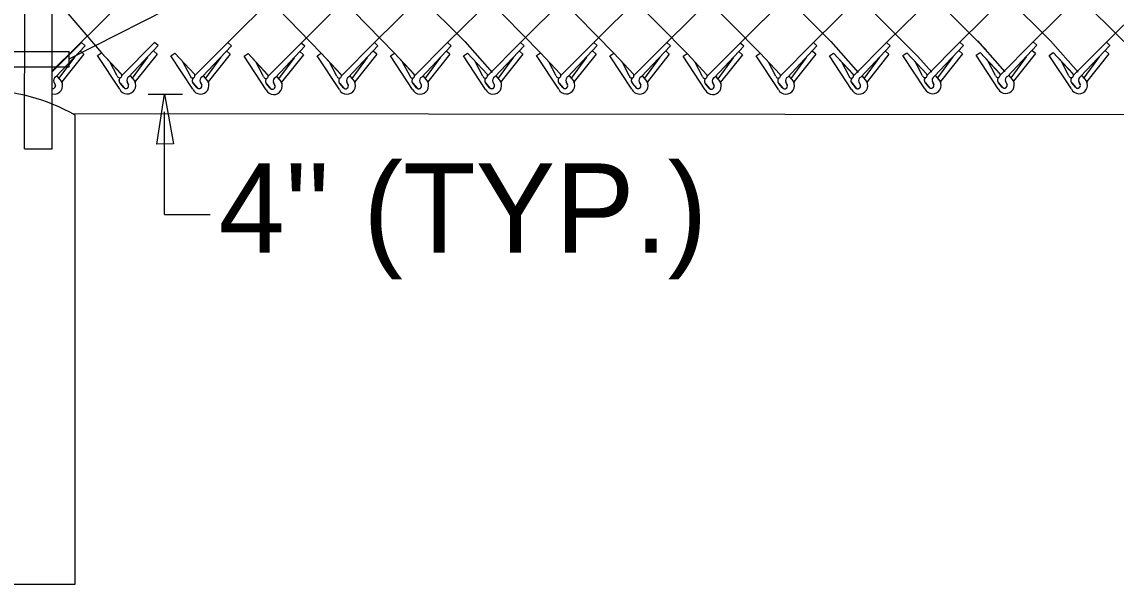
# Model space of a CAD drawing. Extents: x 0 to 1270, y 0 to 830.
# Drawn here: x 53.5 to 113.7, y 352.2 to 383.2 of the extents above; entities that cross this region are included whole.
import ezdxf

# ---------------------------------------------------------------- set-up
doc = ezdxf.new("R2010")
doc.units = 0
for name, color, linetype in [('CT_Dimensions', 7, 'Continuous'), ('sb_Chainlink Fence', 7, 'Continuous'), ('sb_Existing Concrete', 7, 'Continuous'), ('sb_Existing Structural Steel', 7, 'Continuous')]:
    doc.layers.add(name, color=color, linetype=linetype)

msp = doc.modelspace()

# ---------------------------------------------------------------- linework, layer by layer
at = {"layer": 'CT_Dimensions'}
for p, q in [((60.451, 379.198), (62.33, 379.198)), ((61.341, 372.57), (61.341, 378.225)), ((61.341, 372.57), (63.855, 372.57))]:
    msp.add_line(p, q, dxfattribs=at)
msp.add_lwpolyline([(60.924, 376.439), (61.34, 379.193), (61.84, 376.453)], close=True, dxfattribs=at)
at = {"layer": 'sb_Chainlink Fence'}
for p, q in [((60.791, 435.304), (114.124, 382.089)), ((68.863, 382.004), (122.519, 435.835)), ((101.072, 382.029), (154.956, 435.546)), ((64.832, 382.034), (118.139, 435.235)), ((72.891, 382.026), (126.395, 435.183)), ((76.918, 382.029), (130.422, 435.192)), ((80.932, 382.032), (134.453, 435.222)), ((84.959, 382.042), (138.481, 435.199)), ((88.986, 382.034), (142.508, 435.196)), ((93.017, 382.004), (146.522, 435.194)), ((105.111, 382.053), (158.608, 435.222)), ((109.138, 382.063), (162.636, 435.199)), ((113.165, 382.055), (166.662, 435.196)), ((57.834, 434.248), (110.093, 382.118)), ((55.231, 432.935), (106.547, 381.637)), ((97.046, 382.026), (147.698, 432.692)), ((55.226, 428.91), (102.798, 381.262)), ((55.221, 424.884), (98, 382.093)), ((55.216, 420.858), (94.125, 381.448)), ((55.211, 416.833), (90.096, 381.426)), ((55.207, 412.807), (86.065, 381.456)), ((55.202, 408.781), (82.038, 381.464)), ((55.197, 404.755), (77.86, 382.095)), ((55.192, 400.73), (73.996, 381.451)), ((55.187, 396.704), (69.97, 381.448)), ((55.168, 380.467), (59.118, 384.405)), ((55.173, 384.627), (57.883, 381.464)), ((55.164, 380.412), (56.778, 382.032)), ((55.363, 380.139), (56.976, 381.852)), ((56.976, 381.852), (56.778, 382.032)), ((58.991, 380.221), (60.804, 382.042)), ((59.39, 380.149), (61.002, 381.863)), ((61.002, 381.863), (60.804, 382.042)), ((63.018, 380.212), (64.832, 382.034)), ((63.417, 380.141), (65.029, 381.854)), ((65.029, 381.854), (64.832, 382.034)), ((67.049, 380.183), (68.863, 382.004)), ((67.448, 380.111), (69.061, 381.825)), ((69.061, 381.825), (68.863, 382.004)), ((71.077, 380.205), (72.891, 382.026)), ((71.476, 380.134), (73.089, 381.847)), ((73.089, 381.847), (72.891, 382.026)), ((75.104, 380.208), (76.918, 382.029)), ((75.503, 380.136), (77.115, 381.85)), ((77.115, 381.85), (76.918, 382.029)), ((77.86, 382.095), (79.378, 380.386)), ((79.118, 380.21), (80.932, 382.032)), ((79.517, 380.139), (81.13, 381.852)), ((81.13, 381.852), (80.932, 382.032)), ((83.145, 380.221), (84.959, 382.042)), ((83.544, 380.149), (85.157, 381.863)), ((85.157, 381.863), (84.959, 382.042)), ((87.172, 380.212), (88.986, 382.034)), ((87.571, 380.141), (89.184, 381.854)), ((89.184, 381.854), (88.986, 382.034)), ((91.204, 380.183), (93.017, 382.004)), ((91.602, 380.111), (93.215, 381.825)), ((93.215, 381.825), (93.017, 382.004)), ((95.232, 380.205), (97.046, 382.026)), ((95.631, 380.134), (97.243, 381.847)), ((97.243, 381.847), (97.046, 382.026)), ((98, 382.093), (99.518, 380.384)), ((99.258, 380.208), (101.072, 382.029)), ((99.657, 380.136), (101.27, 381.85)), ((101.27, 381.85), (101.072, 382.029)), ((103.297, 380.232), (105.111, 382.053)), ((103.696, 380.16), (105.309, 381.874)), ((105.309, 381.874), (105.111, 382.053)), ((106.066, 382.127), (107.583, 380.418)), ((107.324, 380.242), (109.138, 382.063)), ((107.723, 380.171), (109.336, 381.884)), ((109.336, 381.884), (109.138, 382.063)), ((110.093, 382.118), (111.611, 380.41)), ((111.351, 380.233), (113.165, 382.055)), ((111.75, 380.162), (113.363, 381.876)), ((113.363, 381.876), (113.165, 382.055)), ((56.389, 381.223), (55.54, 380.068)), ((56.908, 381.389), (55.702, 379.872)), ((56.908, 381.389), (56.71, 381.569)), ((57.66, 381.312), (57.883, 381.464)), ((58.879, 379.467), (57.66, 381.312)), ((57.883, 381.464), (58.961, 380.302)), ((57.883, 381.464), (58.968, 380.295)), ((60.416, 381.234), (59.567, 380.079)), ((60.935, 381.4), (59.729, 379.882)), ((60.935, 381.4), (60.737, 381.579)), ((61.688, 381.303), (61.91, 381.456)), ((62.906, 379.459), (61.688, 381.303)), ((61.91, 381.456), (62.988, 380.294)), ((61.91, 381.456), (62.995, 380.287)), ((64.443, 381.225), (63.594, 380.07)), ((64.962, 381.391), (63.756, 379.874)), ((64.962, 381.391), (64.764, 381.571)), ((65.719, 381.274), (65.942, 381.426)), ((66.937, 379.429), (65.719, 381.274)), ((65.942, 381.426), (67.02, 380.264)), ((65.942, 381.426), (67.027, 380.257)), ((68.474, 381.196), (67.625, 380.041)), ((68.993, 381.362), (67.787, 379.844)), ((68.993, 381.362), (68.796, 381.541)), ((69.747, 381.296), (69.97, 381.448)), ((70.965, 379.452), (69.747, 381.296)), ((69.97, 381.448), (71.048, 380.287)), ((69.97, 381.448), (71.055, 380.28)), ((72.502, 381.218), (71.654, 380.063)), ((73.022, 381.384), (71.815, 379.867)), ((73.022, 381.384), (72.824, 381.563)), ((73.774, 381.299), (73.996, 381.451)), ((74.992, 379.454), (73.774, 381.299)), ((73.996, 381.451), (75.074, 380.289)), ((73.996, 381.451), (75.081, 380.282)), ((76.529, 381.221), (75.68, 380.066)), ((77.048, 381.387), (75.842, 379.869)), ((77.048, 381.387), (76.85, 381.566)), ((77.788, 381.301), (78.011, 381.454)), ((79.006, 379.457), (77.788, 381.301)), ((78.011, 381.454), (79.089, 380.292)), ((78.011, 381.454), (79.096, 380.285)), ((80.543, 381.223), (79.695, 380.068)), ((81.063, 381.389), (79.856, 379.872)), ((81.063, 381.389), (80.865, 381.569)), ((81.815, 381.312), (82.038, 381.464)), ((83.033, 379.467), (81.815, 381.312)), ((82.038, 381.464), (83.116, 380.302)), ((82.038, 381.464), (83.123, 380.295)), ((84.57, 381.234), (83.722, 380.079)), ((85.09, 381.4), (83.883, 379.882)), ((85.09, 381.4), (84.892, 381.579)), ((85.842, 381.303), (86.065, 381.456)), ((87.06, 379.459), (85.842, 381.303)), ((86.065, 381.456), (87.143, 380.294)), ((86.065, 381.456), (87.15, 380.287)), ((88.597, 381.225), (87.749, 380.07)), ((89.117, 381.391), (87.91, 379.874)), ((89.117, 381.391), (88.919, 381.571)), ((89.873, 381.274), (90.096, 381.426)), ((91.091, 379.429), (89.873, 381.274)), ((90.096, 381.426), (91.174, 380.264)), ((90.096, 381.426), (91.181, 380.257)), ((92.628, 381.196), (91.78, 380.041)), ((93.148, 381.362), (91.942, 379.844)), ((93.148, 381.362), (92.95, 381.541)), ((93.902, 381.296), (94.125, 381.448)), ((95.12, 379.452), (93.902, 381.296)), ((94.125, 381.448), (95.203, 380.287)), ((94.125, 381.448), (95.209, 380.28)), ((96.657, 381.218), (95.808, 380.063)), ((97.176, 381.384), (95.97, 379.867)), ((97.176, 381.384), (96.978, 381.563)), ((97.928, 381.299), (98.151, 381.451)), ((99.146, 379.454), (97.928, 381.299)), ((98.151, 381.451), (99.229, 380.289)), ((98.151, 381.451), (99.236, 380.282)), ((100.683, 381.221), (99.835, 380.066)), ((101.203, 381.387), (99.996, 379.869)), ((101.203, 381.387), (101.005, 381.566)), ((101.967, 381.323), (102.19, 381.475)), ((103.185, 379.478), (101.967, 381.323)), ((102.19, 381.475), (103.268, 380.313)), ((102.19, 381.475), (103.275, 380.306)), ((102.798, 381.262), (103.557, 380.408)), ((104.722, 381.245), (103.874, 380.09)), ((105.242, 381.411), (104.035, 379.893)), ((105.242, 381.411), (105.044, 381.59)), ((105.994, 381.333), (106.217, 381.485)), ((107.212, 379.488), (105.994, 381.333)), ((106.217, 381.485), (107.295, 380.323)), ((106.217, 381.485), (107.302, 380.317)), ((108.749, 381.255), (107.9, 380.1)), ((109.269, 381.421), (108.062, 379.903)), ((109.269, 381.421), (109.071, 381.6)), ((110.021, 381.325), (110.244, 381.477)), ((111.239, 379.48), (110.021, 381.325)), ((110.244, 381.477), (111.322, 380.315)), ((110.244, 381.477), (111.329, 380.308)), ((112.776, 381.247), (111.928, 380.092)), ((113.296, 381.413), (112.089, 379.895)), ((113.296, 381.413), (113.098, 381.592)), ((58.74, 380.195), (58.334, 380.971)), ((62.767, 380.187), (62.361, 380.962)), ((66.798, 380.157), (66.392, 380.933)), ((70.827, 380.179), (70.421, 380.955)), ((74.853, 380.182), (74.447, 380.958)), ((78.868, 380.185), (78.462, 380.961)), ((82.894, 380.195), (82.489, 380.971)), ((86.922, 380.187), (86.516, 380.962)), ((90.953, 380.157), (90.547, 380.933)), ((94.981, 380.179), (94.575, 380.955)), ((99.008, 380.182), (98.602, 380.958)), ((103.047, 380.206), (102.641, 380.982)), ((107.073, 380.216), (106.667, 380.992)), ((111.1, 380.208), (110.695, 380.984)), ((55.43, 380.187), (55.678, 379.894)), ((59.365, 379.703), (59.284, 379.88)), ((59.457, 380.197), (59.705, 379.904)), ((59.46, 380.193), (59.706, 379.903)), ((59.705, 379.904), (59.723, 379.87)), ((63.484, 380.189), (63.732, 379.896)), ((63.488, 380.184), (63.733, 379.895)), ((63.732, 379.896), (63.75, 379.862)), ((67.515, 380.159), (67.763, 379.866)), ((67.519, 380.155), (67.764, 379.865)), ((71.544, 380.181), (71.791, 379.888)), ((71.547, 380.177), (71.793, 379.887)), ((71.791, 379.888), (71.81, 379.854)), ((75.57, 380.184), (75.818, 379.891)), ((75.574, 380.18), (75.819, 379.89)), ((75.818, 379.891), (75.836, 379.857)), ((79.585, 380.187), (79.832, 379.894)), ((79.588, 380.182), (79.834, 379.893)), ((79.832, 379.894), (79.851, 379.86)), ((83.52, 379.703), (83.438, 379.88)), ((83.612, 380.197), (83.859, 379.904)), ((83.615, 380.193), (83.86, 379.903)), ((83.859, 379.904), (83.877, 379.87)), ((87.639, 380.189), (87.886, 379.896)), ((87.642, 380.184), (87.888, 379.895)), ((87.886, 379.896), (87.905, 379.862)), ((91.67, 380.159), (91.918, 379.866)), ((91.673, 380.155), (91.919, 379.865)), ((95.698, 380.181), (95.946, 379.888)), ((95.702, 380.177), (95.947, 379.887)), ((95.946, 379.888), (95.964, 379.854)), ((99.725, 380.184), (99.972, 379.891)), ((99.728, 380.18), (99.974, 379.89)), ((99.972, 379.891), (99.991, 379.857)), ((103.672, 379.713), (103.59, 379.891)), ((103.591, 379.884), (103.672, 379.718)), ((103.764, 380.208), (104.011, 379.915)), ((103.767, 380.204), (104.013, 379.914)), ((104.011, 379.915), (104.03, 379.881)), ((104.03, 379.881), (104.045, 379.845)), ((107.699, 379.724), (107.617, 379.901)), ((107.617, 379.895), (107.699, 379.728)), ((107.791, 380.218), (108.038, 379.925)), ((107.794, 380.214), (108.039, 379.924)), ((108.038, 379.925), (108.056, 379.891)), ((108.056, 379.891), (108.072, 379.855)), ((111.726, 379.715), (111.644, 379.893)), ((111.645, 379.886), (111.726, 379.719)), ((111.818, 380.21), (112.065, 379.917)), ((111.821, 380.206), (112.067, 379.916)), ((112.065, 379.917), (112.083, 379.883)), ((112.083, 379.883), (112.099, 379.846)), ((55.339, 379.692), (55.257, 379.869)), ((55.257, 379.863), (55.339, 379.696)), ((55.696, 379.86), (55.712, 379.823)), ((59.104, 379.56), (58.902, 379.802)), ((58.902, 379.802), (59.125, 379.538)), ((59.284, 379.873), (59.365, 379.707)), ((59.723, 379.87), (59.738, 379.834)), ((63.132, 379.551), (62.93, 379.793)), ((62.93, 379.793), (63.152, 379.53)), ((63.393, 379.694), (63.311, 379.871)), ((63.311, 379.865), (63.392, 379.698)), ((63.75, 379.862), (63.766, 379.825)), ((67.163, 379.522), (66.961, 379.764)), ((66.961, 379.764), (67.183, 379.5)), ((67.424, 379.664), (67.342, 379.842)), ((67.342, 379.835), (67.424, 379.668)), ((67.763, 379.866), (67.781, 379.832)), ((67.781, 379.832), (67.797, 379.795)), ((71.191, 379.544), (70.989, 379.786)), ((70.989, 379.786), (71.212, 379.522)), ((71.452, 379.687), (71.37, 379.864)), ((71.371, 379.858), (71.452, 379.691)), ((71.81, 379.854), (71.825, 379.818)), ((75.218, 379.547), (75.016, 379.789)), ((75.016, 379.789), (75.238, 379.525)), ((75.479, 379.69), (75.397, 379.867)), ((75.397, 379.861), (75.478, 379.694)), ((75.836, 379.857), (75.852, 379.821)), ((79.232, 379.55), (79.03, 379.791)), ((79.03, 379.791), (79.253, 379.528)), ((79.493, 379.692), (79.411, 379.869)), ((79.412, 379.863), (79.493, 379.696)), ((79.851, 379.86), (79.866, 379.823)), ((83.259, 379.56), (83.057, 379.802)), ((83.057, 379.802), (83.279, 379.538)), ((83.438, 379.873), (83.52, 379.707)), ((83.877, 379.87), (83.893, 379.834)), ((87.286, 379.551), (87.084, 379.793)), ((87.084, 379.793), (87.307, 379.53)), ((87.547, 379.694), (87.465, 379.871)), ((87.466, 379.865), (87.547, 379.698)), ((87.905, 379.862), (87.92, 379.825)), ((91.317, 379.522), (91.115, 379.764)), ((91.115, 379.764), (91.338, 379.5)), ((91.578, 379.664), (91.496, 379.842)), ((91.497, 379.835), (91.578, 379.668)), ((91.918, 379.866), (91.936, 379.832)), ((91.936, 379.832), (91.951, 379.795)), ((95.346, 379.544), (95.144, 379.786)), ((95.144, 379.786), (95.366, 379.522)), ((95.607, 379.687), (95.525, 379.864)), ((95.525, 379.858), (95.606, 379.691)), ((95.964, 379.854), (95.98, 379.818)), ((99.372, 379.547), (99.17, 379.789)), ((99.17, 379.789), (99.393, 379.525)), ((99.633, 379.69), (99.551, 379.867)), ((99.552, 379.861), (99.633, 379.694)), ((99.991, 379.857), (100.006, 379.821)), ((103.411, 379.571), (103.209, 379.813)), ((103.209, 379.813), (103.432, 379.549)), ((107.438, 379.581), (107.236, 379.823)), ((107.236, 379.823), (107.458, 379.559)), ((111.465, 379.573), (111.263, 379.814)), ((111.263, 379.814), (111.485, 379.551)), ((56.277, 378.134), (269.326, 377.936))]:
    msp.add_line(p, q, dxfattribs=at)
for centre, radius, start, end in [((55.271, 379.664), 0.468, 260.29792, 29.22687), ((55.451, 379.949), 0.209, 114.84217, 203.51672), ((58.866, 380.217), 0.128, 189.93044, 40.97854), ((59.032, 379.943), 0.192, 126.99475, 219.79834), ((59.037, 379.943), 0.195, 127.76564, 226.33281), ((59.298, 379.675), 0.468, 206.32022, 29.22687), ((59.478, 379.959), 0.209, 114.84217, 203.51672), ((62.893, 380.209), 0.128, 189.93044, 40.97854), ((63.059, 379.935), 0.192, 126.99475, 219.79834), ((63.065, 379.935), 0.195, 127.76564, 226.33281), ((63.325, 379.666), 0.468, 206.32022, 29.22687), ((63.505, 379.951), 0.209, 114.84217, 203.51672), ((66.924, 380.179), 0.128, 189.93044, 40.97854), ((67.09, 379.905), 0.192, 126.99475, 219.79834), ((67.096, 379.905), 0.195, 127.76564, 226.33281), ((67.536, 379.921), 0.209, 114.84217, 203.51672), ((70.953, 380.201), 0.128, 189.93044, 40.97854), ((71.119, 379.928), 0.192, 126.99475, 219.79834), ((71.124, 379.927), 0.195, 127.76564, 226.33281), ((71.385, 379.659), 0.468, 206.32022, 29.22687), ((71.564, 379.944), 0.209, 114.84217, 203.51672), ((74.979, 380.204), 0.128, 189.93044, 40.97854), ((75.145, 379.93), 0.192, 126.99475, 219.79834), ((75.151, 379.93), 0.195, 127.76564, 226.33281), ((75.411, 379.662), 0.468, 206.32022, 29.22687), ((75.591, 379.946), 0.209, 114.84217, 203.51672), ((78.994, 380.207), 0.128, 189.93044, 40.97854), ((79.16, 379.933), 0.192, 126.99475, 219.79834), ((79.165, 379.933), 0.195, 127.76564, 226.33281), ((79.426, 379.664), 0.468, 206.32022, 29.22687), ((79.605, 379.949), 0.209, 114.84217, 203.51672), ((83.02, 380.217), 0.128, 189.93044, 40.97854), ((83.187, 379.943), 0.192, 126.99475, 219.79834), ((83.192, 379.943), 0.195, 127.76564, 226.33281), ((83.452, 379.675), 0.468, 206.32022, 29.22687), ((83.632, 379.959), 0.209, 114.84217, 203.51672), ((87.047, 380.209), 0.128, 189.93044, 40.97854), ((87.214, 379.935), 0.192, 126.99475, 219.79834), ((87.219, 379.935), 0.195, 127.76564, 226.33281), ((87.479, 379.666), 0.468, 206.32022, 29.22687), ((87.659, 379.951), 0.209, 114.84217, 203.51672), ((91.079, 380.179), 0.128, 189.93044, 40.97854), ((91.245, 379.905), 0.192, 126.99475, 219.79834), ((91.25, 379.905), 0.195, 127.76564, 226.33281), ((91.69, 379.921), 0.209, 114.84217, 203.51672), ((95.107, 380.201), 0.128, 189.93044, 40.97854), ((95.273, 379.928), 0.192, 126.99475, 219.79834), ((95.279, 379.927), 0.195, 127.76564, 226.33281), ((95.539, 379.659), 0.468, 206.32022, 29.22687), ((95.719, 379.944), 0.209, 114.84217, 203.51672), ((99.134, 380.204), 0.128, 189.93044, 40.97854), ((99.3, 379.93), 0.192, 126.99475, 219.79834), ((99.305, 379.93), 0.195, 127.76564, 226.33281), ((99.565, 379.662), 0.468, 206.32022, 29.22687), ((99.745, 379.946), 0.209, 114.84217, 203.51672), ((103.173, 380.228), 0.128, 189.93044, 40.97854), ((103.339, 379.954), 0.192, 126.99475, 219.79834), ((103.344, 379.954), 0.195, 127.76564, 226.33281), ((103.604, 379.686), 0.468, 206.32022, 29.22687), ((103.784, 379.97), 0.209, 114.84217, 203.51672), ((107.199, 380.238), 0.128, 189.93044, 40.97854), ((107.366, 379.964), 0.192, 126.99475, 219.79834), ((107.371, 379.964), 0.195, 127.76564, 226.33281), ((107.631, 379.696), 0.468, 206.32022, 29.22687), ((107.811, 379.981), 0.209, 114.84217, 203.51672), ((111.226, 380.23), 0.128, 189.93044, 40.97854), ((111.393, 379.956), 0.192, 126.99475, 219.79834), ((111.398, 379.956), 0.195, 127.76564, 226.33281), ((111.658, 379.687), 0.468, 206.32022, 29.22687), ((111.838, 379.972), 0.209, 114.84217, 203.51672), ((55.194, 379.647), 0.152, 263.73209, 17.48524), ((55.195, 379.646), 0.152, 302.84789, 19.26564), ((59.221, 379.657), 0.152, 219.86319, 17.48524), ((59.221, 379.656), 0.152, 230.7826, 19.26564), ((63.248, 379.649), 0.152, 219.86319, 17.48524), ((63.249, 379.648), 0.152, 230.7826, 19.26564), ((67.356, 379.637), 0.468, 206.32022, 29.22687), ((67.279, 379.619), 0.152, 219.86319, 17.48524), ((67.28, 379.618), 0.152, 230.7826, 19.26564), ((71.308, 379.641), 0.152, 219.86319, 17.48524), ((71.308, 379.64), 0.152, 230.7826, 19.26564), ((75.334, 379.644), 0.152, 219.86319, 17.48524), ((75.335, 379.643), 0.152, 230.7826, 19.26564), ((79.349, 379.647), 0.152, 219.86319, 17.48524), ((79.349, 379.646), 0.152, 230.7826, 19.26564), ((83.375, 379.657), 0.152, 219.86319, 17.48524), ((83.376, 379.656), 0.152, 230.7826, 19.26564), ((87.402, 379.649), 0.152, 219.86319, 17.48524), ((87.403, 379.648), 0.152, 230.7826, 19.26564), ((91.511, 379.637), 0.468, 206.32022, 29.22687), ((91.434, 379.619), 0.152, 219.86319, 17.48524), ((91.434, 379.618), 0.152, 230.7826, 19.26564), ((95.462, 379.641), 0.152, 219.86319, 17.48524), ((95.463, 379.64), 0.152, 230.7826, 19.26564), ((99.488, 379.644), 0.152, 219.86319, 17.48524), ((99.489, 379.643), 0.152, 230.7826, 19.26564), ((103.527, 379.668), 0.152, 219.86319, 17.48524), ((103.528, 379.667), 0.152, 230.7826, 19.26564), ((107.554, 379.678), 0.152, 219.86319, 17.48524), ((107.555, 379.677), 0.152, 230.7826, 19.26564), ((111.581, 379.67), 0.152, 219.86319, 17.48524), ((111.582, 379.669), 0.152, 230.7826, 19.26564)]:
    msp.add_arc(centre, radius, start, end, dxfattribs=at)
at = {"layer": 'sb_Existing Concrete'}
for p, q in [((56.431, 352.25), (56.426, 378.031)), ((46.326, 352.25), (56.431, 352.25))]:
    msp.add_line(p, q, dxfattribs=at)
msp.add_arc((51.346, 369.249), 10.145, 59.95295, 119.68756, dxfattribs=at)
at = {"layer": 'sb_Existing Structural Steel'}
for p, q in [((53.651, 376.184), (53.739, 433.67)), ((55.159, 376.184), (55.247, 433.67)), ((99.506, 403.229), (56.111, 381.128)), ((53.706, 382.095), (53.706, 382.095)), ((49.395, 381.544), (56.099, 381.544)), ((56.099, 380.699), (56.099, 381.544)), ((49.395, 380.699), (56.099, 380.699)), ((56.099, 380.699), (56.088, 380.706)), ((53.651, 376.184), (55.159, 376.184))]:
    msp.add_line(p, q, dxfattribs=at)

# ---------------------------------------------------------------- texts
at = {"layer": 'CT_Dimensions'}
msp.add_text("4'' (TYP.)", height=4.9005, rotation=360, dxfattribs=at).set_placement((64.314, 370.483))

doc.saveas('drawing.dxf')
